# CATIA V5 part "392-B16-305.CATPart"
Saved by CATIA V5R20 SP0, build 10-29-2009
Part number: 392-B16-305
Definition: NONE
Nomenclature: 392-B16-305
Source: Unknown
Description: 392-B16-305
Bounding box of the stored display mesh (mm): x 0 to 305, y -7.674 to 7.674, z -7.409 to 7.409
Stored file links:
  C:\Users\Utente\Desktop\IO LAVORO\3D X SITO CF\X SITO\3D files 392B\392-B16-305.CATPart
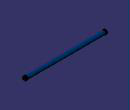
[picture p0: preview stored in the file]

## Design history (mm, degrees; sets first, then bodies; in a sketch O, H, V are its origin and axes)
Body1 "392-B16-305" (main body)
  Solid1: solid without history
